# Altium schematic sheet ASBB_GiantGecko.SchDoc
size A4
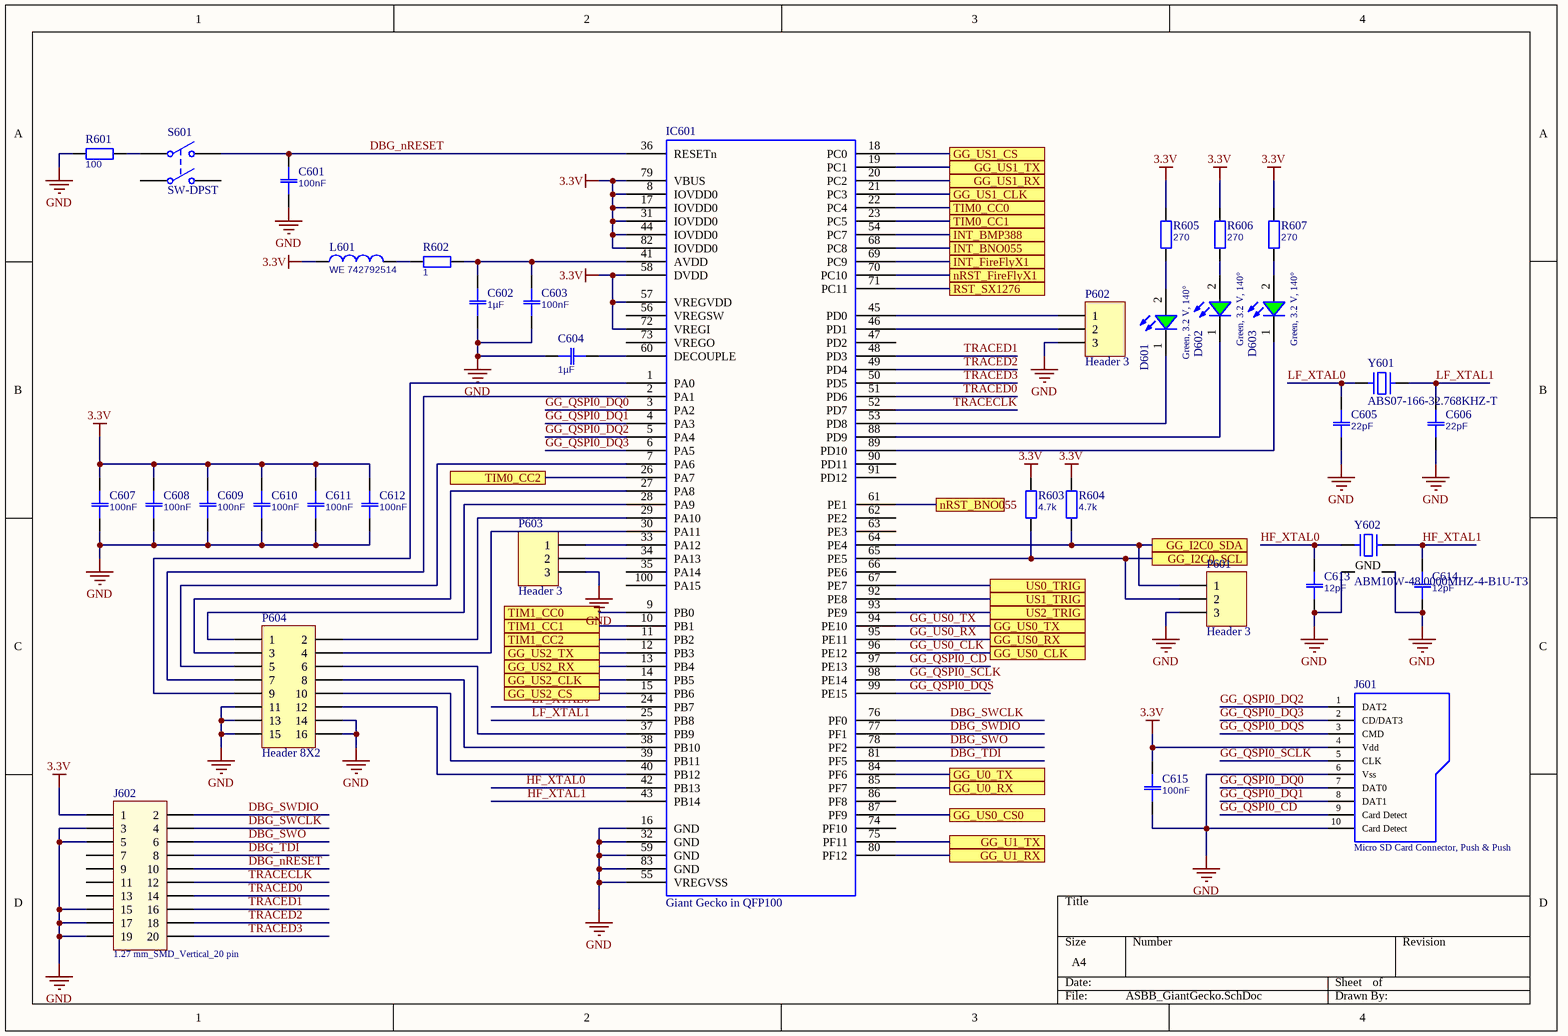
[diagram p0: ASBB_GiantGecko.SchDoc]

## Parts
C601  100nF  [0603]
C602  1µF  [0603]
C603  100nF  [0603]
C604  1µF  [0603]
C605  22pF  [0603]
C606  22pF  [0603]
C607  100nF  [0603]
C608  100nF  [0603]
C609  100nF  [0603]
C610  100nF  [0603]
C611  100nF  [0603]
C612  100nF  [0603]
C613  12pF  [0603]
C614  12pF  [0603]
C615  100nF  [0603]
D601  Green, 3.2 V, 140°  [WL-SMCW_0603]
D602  Green, 3.2 V, 140°  [WL-SMCW_0603]
D603  Green, 3.2 V, 140°  [WL-SMCW_0603]
IC601  Giant Gecko in QFP100  [TQFP100]
J601  Micro SD Card Connector, Push & Push  [693071010811]
J602  1.27 mm_SMD_Vertical_20 pin  [62102021021]
L601  WE 742792514  [1812]
P601  Header 3  [HDR1X3]
P602  Header 3  [HDR1X3]
P603  Header 3  [HDR1X3]
P604  Header 8X2  [HDR2X8]
R601  100  [0603]
R602  1  [0603]
R603  4.7k  [0603]
R604  4.7k  [0603]
R605  270  [0603]
R606  270  [0603]
R607  270  [0603]
S601  SW-DPST  [DPST-4]
Y601  ABS07-166-32.768KHZ-T  [ABRACON ABS07]
Y602  ABM10W-48.0000MHZ-4-B1U-T3  [ABRACON ABM10]

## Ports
GG_I2C0_SCL, GG_I2C0_SDA, GG_U0_RX, GG_U0_TX, GG_U1_RX, GG_U1_TX, GG_US0_CLK, GG_US0_CS0, GG_US0_RX, GG_US0_TX, GG_US1_CLK, GG_US1_CS, GG_US1_RX, GG_US1_TX, GG_US2_CLK, GG_US2_CS, GG_US2_RX, GG_US2_TX, INT_BMP388, INT_BNO055, INT_FireFlyX1, nRST_BNO055, nRST_FireFlyX1, RST_SX1276, TIM0_CC0, TIM0_CC1, TIM0_CC2, TIM1_CC0, TIM1_CC1, TIM1_CC2, US0_TRIG, US1_TRIG, US2_TRIG

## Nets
3.3V: C607.1 C608.1 C609.1 C610.1 C611.1 C612.1 C615.1 IC601.8(IOVDD0) IC601.17(IOVDD0) IC601.31(IOVDD0) IC601.44(IOVDD0) IC601.57(VREGVDD) IC601.58(DVDD) IC601.72(VREGI) IC601.79(VBUS) IC601.82(IOVDD0) J601.4(Vdd) J602.1 L601.1 R603.2 R604.2 R605.2 R606.2 R607.2
GND: C601.2 C602.2 C603.2 C604.1 C605.2 C606.2 C607.2 C608.2 C609.2 C610.2 C611.2 C612.2 C613.2 C614.2 C615.2 IC601.16(GND) IC601.32(GND) IC601.55(VREGVSS) IC601.59(GND) IC601.83(GND) J601.6(Vss) J601.10(Card_Detect) J602.3 J602.5 J602.15 J602.17 J602.19 P601.3 P602.3 P603.3 P604.11 P604.13 P604.14 P604.15 P604.16 R601.1 Y602.2(GND) Y602.4(GND)
DBG_nRESET: C601.1 IC601.36(RESETn) J602.10 S601.2(NO1)
DBG_SWCLK: IC601.76(PF0) J602.4
DBG_SWDIO: IC601.77(PF1) J602.2
DBG_SWO: IC601.78(PF2) J602.6
DBG_TDI: IC601.81(PF5) J602.8
GG_I2C0_SCL: IC601.65(PE5) P601.2 R603.1 ; port GG_I2C0_SCL
GG_I2C0_SDA: IC601.64(PE4) P601.1 R604.1 ; port GG_I2C0_SDA
GG_QSPI0_CD: IC601.97(PE13) J601.9(Card_Detect)
GG_QSPI0_DQ0: IC601.3(PA2) J601.7(DAT0)
GG_QSPI0_DQ1: IC601.4(PA3) J601.8(DAT1)
GG_QSPI0_DQ2: IC601.5(PA4) J601.1(DAT2)
GG_QSPI0_DQ3: IC601.6(PA5) J601.2(CD/DAT3)
GG_QSPI0_DQS: IC601.99(PE15) J601.3(CMD)
GG_QSPI0_SCLK: IC601.98(PE14) J601.5(CLK)
GG_U0_RX: IC601.85(PF7) ; port GG_U0_RX
GG_U0_TX: IC601.84(PF6) ; port GG_U0_TX
GG_U1_RX: IC601.80(PF12) ; port GG_U1_RX
GG_U1_TX: IC601.75(PF11) ; port GG_U1_TX
GG_US0_CLK: IC601.96(PE12) ; port GG_US0_CLK
GG_US0_CS0: IC601.87(PF9) ; port GG_US0_CS0
GG_US0_RX: IC601.95(PE11) ; port GG_US0_RX
GG_US0_TX: IC601.94(PE10) ; port GG_US0_TX
GG_US1_CLK: IC601.21(PC3) ; port GG_US1_CLK
GG_US1_CS: IC601.18(PC0) ; port GG_US1_CS
GG_US1_RX: IC601.20(PC2) ; port GG_US1_RX
GG_US1_TX: IC601.19(PC1) ; port GG_US1_TX
GG_US2_CLK: IC601.14(PB5) ; port GG_US2_CLK
GG_US2_CS: IC601.15(PB6) ; port GG_US2_CS
GG_US2_RX: IC601.13(PB4) ; port GG_US2_RX
GG_US2_TX: IC601.12(PB3) ; port GG_US2_TX
HF_XTAL0: C613.1 IC601.42(PB13) Y602.1
HF_XTAL1: C614.1 IC601.43(PB14) Y602.3
INT_BMP388: IC601.54(PC7) ; port INT_BMP388
INT_BNO055: IC601.68(PC8) ; port INT_BNO055
INT_FireFlyX1: IC601.69(PC9) ; port INT_FireFlyX1
LF_XTAL0: C605.1 IC601.24(PB7) Y601.1
LF_XTAL1: C606.1 IC601.25(PB8) Y601.2
nRST_BNO055: IC601.61(PE1) ; port nRST_BNO055
nRST_FireFlyX1: IC601.70(PC10) ; port nRST_FireFlyX1
RST_SX1276: IC601.71(PC11) ; port RST_SX1276
TIM0_CC0: IC601.22(PC4) ; port TIM0_CC0
TIM0_CC1: IC601.23(PC5) ; port TIM0_CC1
TIM0_CC2: IC601.26(PA7) ; port TIM0_CC2
TIM1_CC0: IC601.9(PB0) ; port TIM1_CC0
TIM1_CC1: IC601.10(PB1) ; port TIM1_CC1
TIM1_CC2: IC601.11(PB2) ; port TIM1_CC2
TRACECLK: IC601.52(PD7) J602.12
TRACED0: IC601.51(PD6) J602.14
TRACED1: IC601.48(PD3) J602.16
TRACED2: IC601.49(PD4) J602.18
TRACED3: IC601.50(PD5) J602.20
US0_TRIG: IC601.67(PE7) ; port US0_TRIG
US1_TRIG: IC601.92(PE8) ; port US1_TRIG
US2_TRIG: IC601.93(PE9) ; port US2_TRIG
NetC602_1: C602.1 C603.1 IC601.41(AVDD) R602.2
NetC604_2: C604.2 IC601.60(DECOUPLE)
NetD601_1: D601.1(K) IC601.53(PD8)
NetD601_2: D601.2(A) R605.1
NetD602_1: D602.1(K) IC601.88(PD9)
NetD602_2: D602.2(A) R606.1
NetD603_1: D603.1(K) IC601.89(PD10)
NetD603_2: D603.2(A) R607.1
NetIC601_1: IC601.1(PA0) P604.9
NetIC601_2: IC601.2(PA1) P604.7
NetIC601_7: IC601.7(PA6) P604.5
NetIC601_27: IC601.27(PA8) P604.3
NetIC601_28: IC601.28(PA9) P604.1
NetIC601_29: IC601.29(PA10) P604.2
NetIC601_30: IC601.30(PA11) P604.4
NetIC601_33: IC601.33(PA12) P603.1
NetIC601_34: IC601.34(PA13) P603.2
NetIC601_37: IC601.37(PB9) P604.6
NetIC601_38: IC601.38(PB10) P604.8
NetIC601_39: IC601.39(PB11) P604.10
NetIC601_40: IC601.40(PB12) P604.12
NetIC601_45: IC601.45(PD0) P602.1
NetIC601_46: IC601.46(PD1) P602.2
NetL601_2: L601.2 R602.1
NetR601_2: R601.2 S601.1(COMMON1)

Not connected (* = marked no-connect by the designer): IC601 35(PA14) 47(PD2) 56(VREGSW) 62(PE2) 63(PE3) 66(PE6) 73(VREGO) 74(PF10) 86(PF8) 90(PD11) 91(PD12) 100(PA15); J602 7 9 11 13; S601 3(COMMON2) 4(NO2)

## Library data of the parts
C601-C615 = Capacitor
D601-D603 = 150060GS75000: WL-SMCW SMD Mono-color Chip LED Waterclear, size 0603, Green, 3.2 V, 140°; Forward Voltage: 3.2 V; Peak Wavelength: 515 nm; Dominant Wavelength: 525 nm; Luminous Intensity: 430 mcd
IC601 = EFM32GG11B8xx
J601 = 693071010811: WR-CRD Micro SD Card Connector, Push & Push, with card detection; Rated Current: 0.5A; Working Voltage: 500V AC
J602 = 62102021021: Pin Header WR-PHD, pitch 1.27 mm, SMD, Vertical, dual row, 20 pin; Rated Current: 1 A; Pin Number: 20; Pitch: 1.27 mm; Working Voltage: 100 VAC; Contact Resistance: 20 mOhm; Insulation Resistance: >1000 MOhm
L601 = Inductor
P601-P603 = Header 3: Header, 3-Pin
P604 = Header 8X2: Header, 8-Pin, Dual row
R601-R607 = Resistor
S601 = SW-DPST: Double-Pole, Single-Throw Switch
Y601 = Abracon Crystal ABS06: SMT Crystal
Y602 = Abracon Crystal ABM10: SMT Crystal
